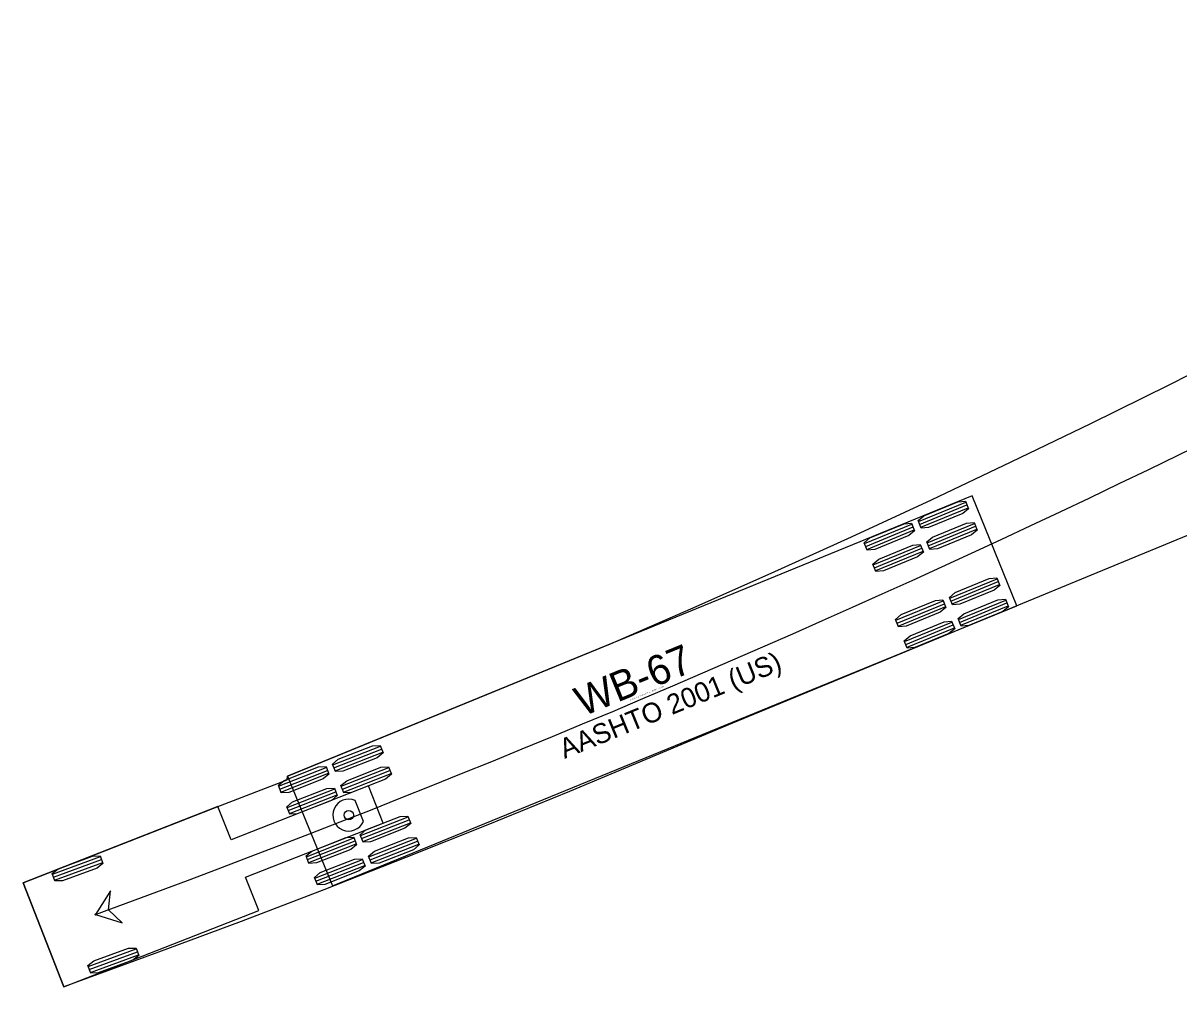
# Model space of a CAD drawing. Extents: x 2175591 to 2194071, y 76570 to 86955.
# Drawn here: x 2193829.3 to 2193912.2, y 86847.3 to 86916.3 of the extents above; entities that cross this region are included whole.
import ezdxf

# ---------------------------------------------------------------- set-up
doc = ezdxf.new("R2010")
doc.units = 0
doc.layers.add('C-UTIL-STRM-TEXT', color=7, linetype='Continuous')

msp = doc.modelspace()

# ---------------------------------------------------------------- linework, layer by layer
at = {"layer": 'C-UTIL-STRM-TEXT'}
for p, q in [((2193897.359, 86882.464), (2193848.302, 86862.404)), ((2193893.512, 86880.643), (2193896.905, 86882.031)), ((2193900.576, 86874.596), (2193897.359, 86882.464)), ((2193893.598, 86880.431), (2193896.992, 86881.819)), ((2193893.685, 86880.219), (2193897.079, 86881.607)), ((2193889.655, 86879.066), (2193893.049, 86880.454)), ((2193894.136, 86879.116), (2193897.53, 86880.504)), ((2193889.742, 86878.854), (2193893.136, 86880.242)), ((2193889.828, 86878.642), (2193893.222, 86880.03)), ((2193894.223, 86878.904), (2193897.617, 86880.292)), ((2193894.31, 86878.692), (2193897.703, 86880.079)), ((2193890.279, 86877.539), (2193893.673, 86878.927)), ((2193890.366, 86877.327), (2193893.76, 86878.714)), ((2193890.453, 86877.115), (2193893.847, 86878.502)), ((2193895.757, 86875.151), (2193899.151, 86876.539)), ((2193895.844, 86874.939), (2193899.238, 86876.327)), ((2193895.931, 86874.727), (2193899.325, 86876.115)), ((2193851.519, 86854.536), (2193900.576, 86874.596)), ((2193891.901, 86873.574), (2193895.294, 86874.962)), ((2193891.987, 86873.362), (2193895.381, 86874.75)), ((2193892.074, 86873.15), (2193895.468, 86874.538)), ((2193896.382, 86873.624), (2193899.776, 86875.012)), ((2193896.469, 86873.412), (2193899.862, 86874.8)), ((2193896.555, 86873.2), (2193899.949, 86874.587)), ((2193892.525, 86872.047), (2193895.919, 86873.435)), ((2193892.612, 86871.835), (2193896.006, 86873.223)), ((2193892.699, 86871.623), (2193896.092, 86873.01)), ((2193851.543, 86863.207), (2193854.957, 86864.546)), ((2193851.627, 86862.994), (2193855.04, 86864.332)), ((2193851.71, 86862.78), (2193855.124, 86864.119)), ((2193847.664, 86861.686), (2193851.078, 86863.025)), ((2193852.145, 86861.671), (2193855.559, 86863.01)), ((2193847.748, 86861.473), (2193851.161, 86862.811)), ((2193847.831, 86861.259), (2193851.245, 86862.598)), ((2193848.302, 86862.404), (2193851.519, 86854.536)), ((2193852.229, 86861.458), (2193855.643, 86862.796)), ((2193852.313, 86861.244), (2193855.726, 86862.583)), ((2193854.103, 86861.7), (2193844.25, 86857.836)), ((2193848.266, 86860.15), (2193851.68, 86861.488)), ((2193848.35, 86859.936), (2193851.764, 86861.275)), ((2193855.15, 86859.031), (2193854.103, 86861.7)), ((2193848.434, 86859.723), (2193851.847, 86861.062)), ((2193853.734, 86859.148), (2193853.144, 86860.653)), ((2193843.313, 86860.226), (2193829.349, 86854.75)), ((2193844.25, 86857.836), (2193843.313, 86860.226)), ((2193845.297, 86855.168), (2193855.15, 86859.031)), ((2193853.527, 86858.149), (2193856.94, 86859.487)), ((2193853.61, 86857.935), (2193857.024, 86859.274)), ((2193853.694, 86857.722), (2193857.108, 86859.061)), ((2193849.648, 86856.628), (2193853.061, 86857.966)), ((2193854.129, 86856.613), (2193857.543, 86857.951)), ((2193849.731, 86856.414), (2193853.145, 86857.753)), ((2193849.815, 86856.201), (2193853.229, 86857.54)), ((2193854.213, 86856.399), (2193857.626, 86857.738)), ((2193854.296, 86856.186), (2193857.71, 86857.525)), ((2193831.449, 86855.374), (2193834.894, 86856.631)), ((2193831.528, 86855.159), (2193834.973, 86856.416)), ((2193850.25, 86855.092), (2193853.664, 86856.43)), ((2193831.607, 86854.943), (2193835.051, 86856.2)), ((2193850.334, 86854.878), (2193853.747, 86856.217)), ((2193850.417, 86854.665), (2193853.831, 86856.003)), ((2193829.349, 86854.75), (2193832.27, 86847.302)), ((2193846.234, 86852.778), (2193845.297, 86855.168)), ((2193851.519, 86854.536), (2193851.519, 86854.536)), ((2193832.27, 86847.302), (2193846.234, 86852.778)), ((2193834.015, 86848.772), (2193837.46, 86850.029)), ((2193834.094, 86848.556), (2193837.538, 86849.814)), ((2193834.172, 86848.341), (2193837.617, 86849.598)), ((2193832.27, 86847.302), (2193832.27, 86847.302))]:
    msp.add_line(p, q, dxfattribs=at)
msp.add_lwpolyline([(2193915.053, 86880.554), (2193880.179, 86866.198), (2193868.52, 86861.305), (2193862.664, 86858.91), (2193856.789, 86856.559), (2193850.895, 86854.253), (2193844.983, 86851.991), (2193839.057, 86849.776), (2193832.27, 86847.302), (2193829.349, 86854.75), (2193843.502, 86860.298), (2193848.268, 86862.127), (2193848.302, 86862.404), (2193871.443, 86871.877), (2193877.213, 86874.378), (2193882.968, 86876.928), (2193888.725, 86879.537), (2193894.461, 86882.194), (2193900.174, 86884.9), (2193905.863, 86887.655), (2193911.527, 86890.456), (2193917.163, 86893.304)], dxfattribs=at)
for points in [[(2193893.707, 86880.166), (2193893.49, 86880.696), (2193893.9, 86881.049), (2193896.344, 86882.049), (2193896.884, 86882.083), (2193897.1, 86881.554), (2193896.691, 86881.2), (2193894.247, 86880.201)], [(2193889.85, 86878.589), (2193889.633, 86879.119), (2193890.043, 86879.472), (2193892.487, 86880.472), (2193893.027, 86880.506), (2193893.244, 86879.977), (2193892.834, 86879.623), (2193890.39, 86878.624)], [(2193894.331, 86878.639), (2193894.115, 86879.168), (2193894.524, 86879.522), (2193896.968, 86880.521), (2193897.508, 86880.556), (2193897.725, 86880.027), (2193897.315, 86879.673), (2193894.871, 86878.674)], [(2193890.474, 86877.062), (2193890.258, 86877.591), (2193890.668, 86877.945), (2193893.111, 86878.944), (2193893.652, 86878.979), (2193893.868, 86878.45), (2193893.458, 86878.096), (2193891.015, 86877.097)], [(2193895.952, 86874.674), (2193895.736, 86875.204), (2193896.146, 86875.558), (2193898.589, 86876.557), (2193899.13, 86876.592), (2193899.346, 86876.062), (2193898.936, 86875.708), (2193896.493, 86874.709)], [(2193892.096, 86873.097), (2193891.879, 86873.627), (2193892.289, 86873.981), (2193894.733, 86874.98), (2193895.273, 86875.015), (2193895.489, 86874.485), (2193895.08, 86874.131), (2193892.636, 86873.132)], [(2193896.577, 86873.147), (2193896.36, 86873.677), (2193896.77, 86874.03), (2193899.214, 86875.03), (2193899.754, 86875.064), (2193899.971, 86874.535), (2193899.561, 86874.181), (2193897.117, 86873.182)], [(2193892.72, 86871.57), (2193892.504, 86872.099), (2193892.914, 86872.453), (2193895.357, 86873.452), (2193895.897, 86873.487), (2193896.114, 86872.958), (2193895.704, 86872.604), (2193893.26, 86871.605)], [(2193851.731, 86862.728), (2193851.522, 86863.26), (2193851.937, 86863.608), (2193854.395, 86864.572), (2193854.936, 86864.599), (2193855.145, 86864.066), (2193854.73, 86863.718), (2193852.272, 86862.754)], [(2193847.852, 86861.206), (2193847.643, 86861.739), (2193848.058, 86862.087), (2193850.516, 86863.051), (2193851.057, 86863.077), (2193851.266, 86862.545), (2193850.851, 86862.197), (2193848.393, 86861.233)], [(2193852.334, 86861.191), (2193852.125, 86861.724), (2193852.54, 86862.072), (2193854.998, 86863.036), (2193855.538, 86863.063), (2193855.747, 86862.53), (2193855.332, 86862.182), (2193852.874, 86861.218)], [(2193848.455, 86859.67), (2193848.246, 86860.203), (2193848.661, 86860.551), (2193851.118, 86861.514), (2193851.659, 86861.541), (2193851.868, 86861.009), (2193851.453, 86860.661), (2193848.995, 86859.697)], [(2193853.715, 86857.669), (2193853.506, 86858.202), (2193853.921, 86858.55), (2193856.379, 86859.513), (2193856.92, 86859.54), (2193857.128, 86859.008), (2193856.713, 86858.66), (2193854.256, 86857.696)], [(2193849.836, 86856.148), (2193849.627, 86856.681), (2193850.042, 86857.028), (2193852.5, 86857.992), (2193853.041, 86858.019), (2193853.249, 86857.487), (2193852.834, 86857.139), (2193850.377, 86856.175)], [(2193854.317, 86856.133), (2193854.108, 86856.666), (2193854.523, 86857.013), (2193856.981, 86857.977), (2193857.522, 86858.004), (2193857.731, 86857.472), (2193857.316, 86857.124), (2193854.858, 86856.16)], [(2193831.626, 86854.89), (2193831.43, 86855.427), (2193831.853, 86855.765), (2193834.333, 86856.67), (2193834.875, 86856.684), (2193835.071, 86856.147), (2193834.647, 86855.809), (2193832.167, 86854.904)], [(2193850.438, 86854.612), (2193850.229, 86855.144), (2193850.644, 86855.492), (2193853.102, 86856.456), (2193853.643, 86856.483), (2193853.852, 86855.951), (2193853.437, 86855.603), (2193850.979, 86854.639)], [(2193834.533, 86852.486), (2193836.441, 86851.886), (2193835.472, 86852.829), (2193835.606, 86854.174)], [(2193834.192, 86848.288), (2193833.996, 86848.825), (2193834.419, 86849.163), (2193836.899, 86850.068), (2193837.44, 86850.082), (2193837.636, 86849.545), (2193837.213, 86849.207), (2193834.733, 86848.302)]]:
    msp.add_lwpolyline(points, close=True, dxfattribs=at)
for centre, radius in [((2193852.687, 86859.605), 0.34), ((2193834.533, 86852.486), 0.0417)]:
    msp.add_circle(centre, radius, dxfattribs=at)
for centre, radius, start, end in [((2193551.13, 87629.029), 826.641, 290.04978, 300.44028), ((2193852.687, 86859.605), 1.143, 66.41299, 336.41299)]:
    msp.add_arc(centre, radius, start, end, dxfattribs=at)

# ---------------------------------------------------------------- texts
for s, height, p in [('AASHTO 2001 (US)', 1.41667, (2193868.151, 86863.625)), ('WB-67', 2.125, (2193869.457, 86866.646)), ('(c) 2019 Transoft Solutions, Inc. All rights reserved.', 0.085, (2193872.851, 86867.805))]:
    msp.add_text(s, height=height, rotation=22.2404, dxfattribs=at).set_placement(p)

doc.saveas('drawing.dxf')
